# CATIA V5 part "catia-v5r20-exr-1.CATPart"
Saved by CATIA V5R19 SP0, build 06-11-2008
Part number: Part1
Bounding box of the stored display mesh (mm): x 0 to 0, y 0 to 100, z 0 to 90
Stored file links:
  D:\Shriniwas\v5_r19\Part files\c02\exe1.CATPart
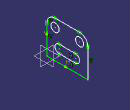
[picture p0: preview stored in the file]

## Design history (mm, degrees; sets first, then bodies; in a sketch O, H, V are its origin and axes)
Body1 (main body)
  Sketch1 on yz-plane, origin (0, 0, 0), H (0, 1, 0), V (0, 0, 1)
    point P1 (0, 70)
    line L1 (0, 70) -> (0, 0)
    line L2 (0, 0) -> (100, 0)
    line L3 (100, 0) -> (100, 70)
    arc A1 centre (80, 70) radius 20 from (100, 70) to (80, 90) ccw
    line L4 (80, 90) -> (20, 90)
    arc A2 centre (20, 70) radius 20 from (20, 90) to (0, 70) ccw
    circle A3 centre (20, 70) radius 10
    circle A4 centre (80, 70) radius 10
    line L5 (30, 20) -> (70, 20)
    arc A5 centre (70, 30) radius 10 from (70, 20) to (70, 40) ccw
    line L6 (70, 40) -> (30, 40)
    arc A6 centre (30, 30) radius 10 from (30, 40) to (30, 20) ccw
    coincidence: P1 V
    vertical: L1 V, L3 V
    horizontal: L2 H, L5 H
    tangency: A1 L3, L4 A1, A2 L1, A2 L4, A5 L5, L6 A5, A6 L5, A6 L6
